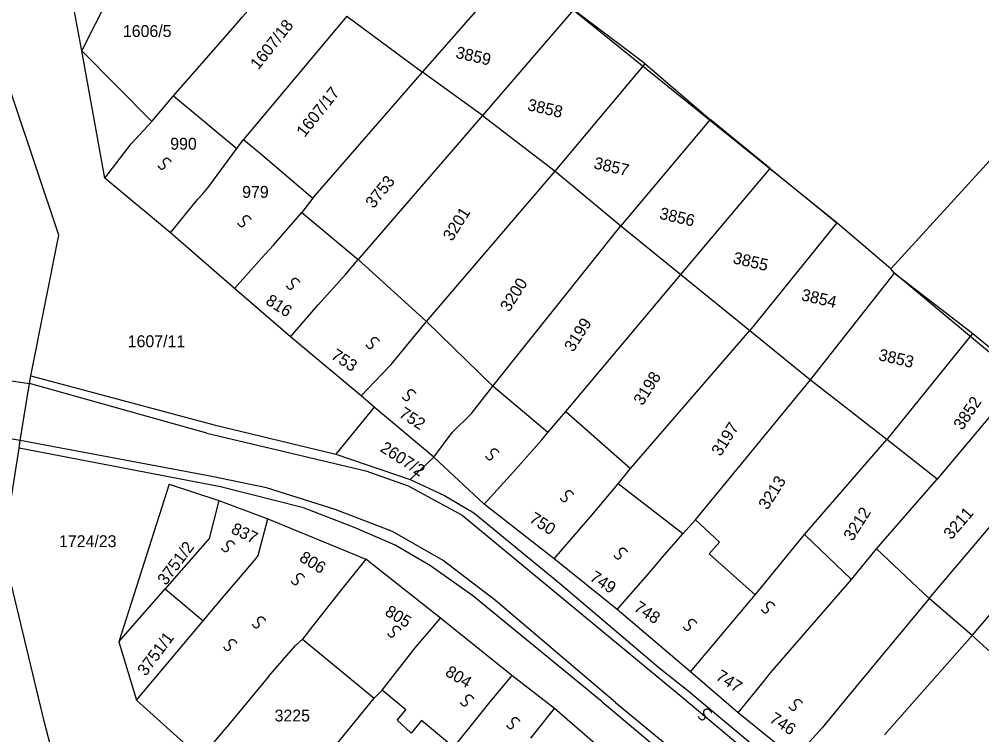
# Model space of a CAD drawing. Extents: x -581999 to -572728, y -1219553 to -1212032.
# Drawn here: x -578616.8 to -578454.7, y -1215447.1 to -1215326.8 of the extents above; entities that cross this region are included whole.
import ezdxf

# ---------------------------------------------------------------- set-up
doc = ezdxf.new("R2010")
doc.units = 0
for name, color, linetype in [('Vrstva 1', 7, 'Continuous'), ('Vrstva 2', 7, 'Continuous'), ('Vrstva 4', 7, 'Continuous'), ('Vrstva 6', 7, 'Continuous'), ('Vrstva 63', 7, 'Continuous')]:
    doc.layers.add(name, color=color, linetype=linetype)

msp = doc.modelspace()

# ---------------------------------------------------------------- linework, layer by layer
at = {"layer": 'Vrstva 1'}
for p, q in [((-578606.252, -1215332.04), (-578615.797, -1215279.788)), ((-578606.252, -1215332.04), (-578595.304, -1215310.421)), ((-578602.345, -1215353.491), (-578606.252, -1215332.04)), ((-578594.44, -1215343.93), (-578606.252, -1215332.04)), ((-578616.594, -1215397.628), (-578615.047, -1215388.059)), ((-578545.855, -1215427.531), (-578558.395, -1215417.606)), ((-578533.826, -1215437.135), (-578545.855, -1215427.531)), ((-578574.718, -1215437.276), (-578570.244, -1215432.113))]:
    msp.add_line(p, q, dxfattribs=at)
for points in [[(-578614.8, -1215386.733), (-578610.127, -1215363.104), (-578625.552, -1215317.149), (-578638.443, -1215277), (-578660.875, -1215206.543)], [(-578470.005, -1215368.724), (-578419.996, -1215313.968), (-578364.405, -1215360.703), (-578359.63, -1215364.861), (-578404.474, -1215421.622)], [(-578548.894, -1215335.635), (-578533.007, -1215317.54)], [(-578580.387, -1215327.793), (-578579.171, -1215326.365), (-578572.028, -1215318.28)], [(-578523.429, -1215325.172), (-578538.8, -1215342.955)], [(-578511.374, -1215334.248), (-578523.429, -1215325.172)], [(-578561.596, -1215326.225), (-578579.014, -1215346.957)], [(-578561.596, -1215326.225), (-578548.894, -1215335.635)], [(-578590.79, -1215339.631), (-578580.387, -1215327.793)], [(-578526.545, -1215352.298), (-578511.374, -1215334.248)], [(-578511.374, -1215334.248), (-578500.443, -1215343.601)], [(-578567.343, -1215356.878), (-578548.894, -1215335.635)], [(-578538.8, -1215342.955), (-578548.894, -1215335.635)], [(-578597.909, -1215347.696), (-578594.44, -1215343.93), (-578590.79, -1215339.631)], [(-578590.79, -1215339.631), (-578580.148, -1215348.51)], [(-578538.8, -1215342.955), (-578559.727, -1215367.161)], [(-578538.8, -1215342.955), (-578526.545, -1215352.298)], [(-578500.443, -1215343.601), (-578515.501, -1215361.486)], [(-578490.342, -1215351.838), (-578500.443, -1215343.601)], [(-578591.29, -1215362.681), (-578602.345, -1215353.491), (-578597.909, -1215347.696)], [(-578584.997, -1215355.131), (-578580.148, -1215348.51)], [(-578580.148, -1215348.51), (-578579.014, -1215346.957)], [(-578579.014, -1215346.957), (-578575.776, -1215349.701)], [(-578575.776, -1215349.701), (-578567.343, -1215356.878)], [(-578548.205, -1215377.626), (-578526.545, -1215352.298)], [(-578526.545, -1215352.298), (-578515.501, -1215361.486)], [(-578505.375, -1215369.692), (-578490.342, -1215351.838)], [(-578490.342, -1215351.838), (-578479.131, -1215361.016)], [(-578591.29, -1215362.681), (-578586.751, -1215357.096), (-578585.874, -1215356.114)], [(-578585.874, -1215356.114), (-578584.997, -1215355.131)], [(-578567.343, -1215356.878), (-578569.199, -1215359.257)], [(-578573.945, -1215364.737), (-578569.199, -1215359.257)], [(-578569.199, -1215359.257), (-578559.727, -1215367.161)], [(-578537.044, -1215388.461), (-578515.501, -1215361.486)], [(-578515.501, -1215361.486), (-578505.375, -1215369.692)], [(-578479.131, -1215361.016), (-578493.773, -1215379.106)], [(-578470.005, -1215368.724), (-578479.131, -1215361.016)], [(-578580.547, -1215372.077), (-578591.29, -1215362.681)], [(-578575.905, -1215366.907), (-578573.945, -1215364.737)], [(-578580.547, -1215372.077), (-578575.905, -1215366.907)], [(-578561.791, -1215369.643), (-578559.727, -1215367.161)], [(-578559.727, -1215367.161), (-578548.205, -1215377.626)], [(-578483.538, -1215387.437), (-578469.436, -1215369.468)], [(-578469.436, -1215369.468), (-578470.005, -1215368.724)], [(-578469.436, -1215369.468), (-578456.237, -1215379.595)], [(-578566.432, -1215374.811), (-578561.791, -1215369.643)], [(-578524.764, -1215392.742), (-578505.375, -1215369.692)], [(-578505.375, -1215369.692), (-578493.773, -1215379.106)], [(-578571.074, -1215380.187), (-578580.547, -1215372.077)], [(-578571.074, -1215380.187), (-578566.432, -1215374.811)], [(-578554.145, -1215384.833), (-578548.205, -1215377.626)], [(-578537.044, -1215388.461), (-578548.205, -1215377.626)], [(-578513.881, -1215402.358), (-578493.773, -1215379.106)], [(-578493.773, -1215379.106), (-578483.538, -1215387.437)], [(-578559.199, -1215390.103), (-578571.074, -1215380.187)], [(-578483.538, -1215387.437), (-578470.672, -1215397.474), (-578456.237, -1215379.595)], [(-578456.237, -1215379.595), (-578447.578, -1215386.69)], [(-578555.693, -1215386.383), (-578554.145, -1215384.833)], [(-578615.047, -1215388.059), (-578614.8, -1215386.733)], [(-578614.8, -1215386.733), (-578583.973, -1215394.99), (-578563.489, -1215399.933)], [(-578559.199, -1215390.103), (-578555.693, -1215386.383)], [(-578502.908, -1215410.958), (-578483.538, -1215387.437)], [(-578447.578, -1215386.69), (-578462.217, -1215404.152)], [(-578540.622, -1215393.077), (-578537.044, -1215388.461)], [(-578527.797, -1215396.276), (-578537.044, -1215388.461)], [(-578557.027, -1215392.021), (-578559.199, -1215390.103)], [(-578557.027, -1215392.021), (-578563.489, -1215399.933)], [(-578546.985, -1215400.41), (-578557.027, -1215392.021)], [(-578543.903, -1215396.261), (-578540.622, -1215393.077)], [(-578527.797, -1215396.276), (-578524.764, -1215392.742)], [(-578524.764, -1215392.742), (-578513.881, -1215402.358)], [(-578463.566, -1215424.184), (-578438.296, -1215394.446)], [(-578546.985, -1215400.41), (-578543.903, -1215396.261)], [(-578528.785, -1215397.496), (-578527.797, -1215396.276)], [(-578612.489, -1215445.07), (-578619.496, -1215416.092), (-578616.755, -1215398.896), (-578616.594, -1215397.628)], [(-578533.529, -1215402.87), (-578528.785, -1215397.496)], [(-578484.566, -1215413.419), (-578470.698, -1215397.462)], [(-578462.217, -1215404.152), (-578470.698, -1215397.462)], [(-578518.647, -1215441.616), (-578540.386, -1215423.773), (-578547.549, -1215418.731), (-578553.493, -1215415.217), (-578560.199, -1215412.314), (-578568.886, -1215408.953), (-578582.907, -1215405.439), (-578616.755, -1215398.896)], [(-578563.489, -1215399.933), (-578550.961, -1215404.178)], [(-578546.985, -1215400.41), (-578550.961, -1215404.178)], [(-578538.479, -1215408.347), (-578546.985, -1215400.41)], [(-578456.35, -1215430.437), (-578436.168, -1215406.937), (-578430.602, -1215400.268)], [(-578538.479, -1215408.347), (-578533.529, -1215402.87)], [(-578515.944, -1215404.943), (-578513.881, -1215402.358)], [(-578591.531, -1215404.968), (-578599.971, -1215431.515)], [(-578591.531, -1215404.968), (-578583.169, -1215407.743)], [(-578550.961, -1215404.178), (-578545.195, -1215406.88), (-578540.223, -1215409.775), (-578525.508, -1215421.836), (-578509.102, -1215435.826), (-578504.23, -1215439.686)], [(-578520.628, -1215410.507), (-578515.944, -1215404.943)], [(-578505.073, -1215413.334), (-578515.944, -1215404.943)], [(-578472.452, -1215415.849), (-578462.217, -1215404.152)], [(-578583.169, -1215407.743), (-578584.817, -1215414.089)], [(-578583.169, -1215407.743), (-578574.905, -1215410.811)], [(-578526.712, -1215417.534), (-578538.479, -1215408.347)], [(-578576.943, -1215417.545), (-578576.554, -1215416.961), (-578574.905, -1215410.811)], [(-578574.905, -1215410.811), (-578558.395, -1215417.606)], [(-578526.712, -1215417.534), (-578521.453, -1215411.437)], [(-578521.453, -1215411.437), (-578520.628, -1215410.507)], [(-578505.073, -1215413.334), (-578502.908, -1215410.958)], [(-578502.908, -1215410.958), (-578498.886, -1215414.711), (-578500.639, -1215416.673), (-578492.865, -1215423.599)], [(-578508.476, -1215417.26), (-578505.073, -1215413.334)], [(-578584.817, -1215414.089), (-578592.2, -1215422.558)], [(-578493.431, -1215424.271), (-578492.865, -1215423.599), (-578492.297, -1215422.928), (-578484.566, -1215413.419)], [(-578484.566, -1215413.419), (-578476.65, -1215420.991)], [(-578476.65, -1215420.991), (-578472.452, -1215415.849)], [(-578472.452, -1215415.849), (-578463.566, -1215424.184)], [(-578585.781, -1215427.963), (-578582.551, -1215424.087), (-578576.943, -1215417.545)], [(-578558.395, -1215417.606), (-578562.96, -1215423.252)], [(-578516.106, -1215426.043), (-578526.712, -1215417.534)], [(-578510.951, -1215420.153), (-578508.476, -1215417.26)], [(-578516.106, -1215426.043), (-578510.951, -1215420.153)], [(-578490.266, -1215436.716), (-578476.65, -1215420.991)], [(-578599.971, -1215431.515), (-578592.2, -1215422.558)], [(-578592.2, -1215422.558), (-578585.781, -1215427.963)], [(-578562.96, -1215423.252), (-578566.942, -1215428.317)], [(-578499.926, -1215432.02), (-578493.431, -1215424.271)], [(-578463.566, -1215424.184), (-578477.791, -1215441.334)], [(-578456.35, -1215430.437), (-578463.566, -1215424.184)], [(-578503.741, -1215436.566), (-578516.106, -1215426.043)], [(-578550.128, -1215432.495), (-578545.855, -1215427.531)], [(-578597.048, -1215441.301), (-578585.781, -1215427.963)], [(-578566.942, -1215428.317), (-578569.078, -1215431.042)], [(-578569.078, -1215431.042), (-578570.244, -1215432.113)], [(-578569.078, -1215431.042), (-578557.023, -1215440.965)], [(-578471.09, -1215447.169), (-578456.35, -1215430.437)], [(-578447.102, -1215438.847), (-578456.35, -1215430.437)], [(-578599.971, -1215431.515), (-578597.048, -1215441.301)], [(-578555.663, -1215439.603), (-578550.128, -1215432.495)], [(-578503.741, -1215436.566), (-578499.926, -1215432.02)], [(-578574.718, -1215437.276), (-578581.217, -1215445.06)], [(-578533.826, -1215437.135), (-578537.517, -1215441.612)], [(-578519.857, -1215448.603), (-578526.636, -1215442.735), (-578533.826, -1215437.135)], [(-578495.73, -1215443.433), (-578503.741, -1215436.566)], [(-578495.73, -1215443.433), (-578491.504, -1215438.266), (-578490.885, -1215437.491)], [(-578490.885, -1215437.491), (-578490.266, -1215436.716)], [(-578557.023, -1215440.965), (-578555.663, -1215439.603)], [(-578551.677, -1215442.943), (-578555.663, -1215439.603)], [(-578504.23, -1215439.686), (-578419.077, -1215510.839)], [(-578597.048, -1215441.301), (-578586.268, -1215450.998)], [(-578573.725, -1215461.408), (-578570.297, -1215457.307), (-578557.023, -1215440.965)], [(-578537.517, -1215441.612), (-578538.876, -1215443.267)], [(-578518.647, -1215441.616), (-578481.363, -1215472.872)], [(-578477.791, -1215441.334), (-578481.605, -1215445.983)], [(-578543.634, -1215449.206), (-578549.054, -1215444.712), (-578550.802, -1215446.854), (-578553.134, -1215444.694), (-578551.677, -1215442.943)], [(-578538.876, -1215443.267), (-578543.634, -1215449.206)], [(-578530.616, -1215447.699), (-578526.636, -1215442.735)], [(-578486.244, -1215451.147), (-578495.73, -1215443.433)], [(-578609.763, -1215455.623), (-578612.489, -1215445.07)], [(-578581.217, -1215445.06), (-578586.268, -1215450.998)], [(-578481.605, -1215445.983), (-578486.244, -1215451.147)]]:
    msp.add_lwpolyline(points, dxfattribs=at)
at = {"layer": 'Vrstva 4'}
for points in [[(-578621.211, -1215387.123), (-578615.047, -1215388.059)], [(-578585.165, -1215396.363), (-578615.047, -1215388.059)], [(-578616.594, -1215397.628), (-578623.694, -1215396.422)], [(-578585.165, -1215396.363), (-578558.419, -1215402.731), (-578551.26, -1215405.24), (-578542.212, -1215410.161), (-578505.224, -1215440.747)], [(-578584.369, -1215403.696), (-578616.594, -1215397.628)], [(-578516.36, -1215441.712), (-578536.576, -1215424.537), (-578545.415, -1215417.814), (-578553.95, -1215412.925), (-578563.552, -1215409.258), (-578575.135, -1215405.592), (-578584.369, -1215403.696)], [(-578505.224, -1215440.747), (-578421.464, -1215511.032)], [(-578516.36, -1215441.712), (-578479.233, -1215472.341)]]:
    msp.add_lwpolyline(points, dxfattribs=at)
at = {"layer": 'Vrstva 6'}
for points in [[(-578593.433, -1215351.395), (-578592.953, -1215352.102), (-578592.259, -1215351.791), (-578592.182, -1215351.391), (-578592.418, -1215351.046), (-578592.503, -1215350.714), (-578592.421, -1215350.424), (-578592.277, -1215350.244), (-578592.041, -1215350.116), (-578591.676, -1215350.152), (-578591.249, -1215350.591), (-578591.194, -1215350.764)], [(-578580.006, -1215361.056), (-578579.526, -1215361.763), (-578578.832, -1215361.452), (-578578.755, -1215361.052), (-578578.991, -1215360.707), (-578579.076, -1215360.375), (-578578.994, -1215360.085), (-578578.85, -1215359.905), (-578578.614, -1215359.777), (-578578.249, -1215359.813), (-578577.822, -1215360.252), (-578577.767, -1215360.425)], [(-578571.833, -1215371.595), (-578571.353, -1215372.302), (-578570.659, -1215371.991), (-578570.582, -1215371.591), (-578570.818, -1215371.246), (-578570.903, -1215370.914), (-578570.821, -1215370.624), (-578570.677, -1215370.444), (-578570.441, -1215370.316), (-578570.076, -1215370.352), (-578569.649, -1215370.791), (-578569.594, -1215370.964)], [(-578558.407, -1215381.549), (-578557.927, -1215382.256), (-578557.233, -1215381.945), (-578557.156, -1215381.545), (-578557.392, -1215381.2), (-578557.477, -1215380.868), (-578557.395, -1215380.578), (-578557.251, -1215380.398), (-578557.015, -1215380.27), (-578556.65, -1215380.306), (-578556.223, -1215380.745), (-578556.168, -1215380.918)], [(-578552.277, -1215390.332), (-578551.797, -1215391.039), (-578551.103, -1215390.728), (-578551.026, -1215390.328), (-578551.262, -1215389.983), (-578551.347, -1215389.651), (-578551.265, -1215389.361), (-578551.121, -1215389.181), (-578550.885, -1215389.053), (-578550.52, -1215389.089), (-578550.093, -1215389.528), (-578550.038, -1215389.701)], [(-578538.267, -1215400.286), (-578537.787, -1215400.993), (-578537.093, -1215400.682), (-578537.016, -1215400.282), (-578537.252, -1215399.937), (-578537.337, -1215399.605), (-578537.255, -1215399.315), (-578537.111, -1215399.135), (-578536.875, -1215399.007), (-578536.51, -1215399.043), (-578536.083, -1215399.482), (-578536.028, -1215399.655)], [(-578525.716, -1215407.312), (-578525.236, -1215408.019), (-578524.542, -1215407.708), (-578524.465, -1215407.308), (-578524.701, -1215406.963), (-578524.786, -1215406.631), (-578524.704, -1215406.341), (-578524.56, -1215406.161), (-578524.324, -1215406.033), (-578523.959, -1215406.069), (-578523.532, -1215406.508), (-578523.477, -1215406.681)], [(-578582.743, -1215415.747), (-578582.263, -1215416.454), (-578581.569, -1215416.143), (-578581.492, -1215415.743), (-578581.728, -1215415.398), (-578581.813, -1215415.066), (-578581.731, -1215414.776), (-578581.587, -1215414.596), (-578581.351, -1215414.468), (-578580.986, -1215414.504), (-578580.559, -1215414.943), (-578580.504, -1215415.116)], [(-578516.667, -1215416.973), (-578516.187, -1215417.68), (-578515.493, -1215417.369), (-578515.416, -1215416.969), (-578515.652, -1215416.624), (-578515.737, -1215416.292), (-578515.655, -1215416.002), (-578515.511, -1215415.822), (-578515.275, -1215415.694), (-578514.91, -1215415.73), (-578514.483, -1215416.169), (-578514.428, -1215416.342)], [(-578571.006, -1215421.283), (-578570.526, -1215421.99), (-578569.832, -1215421.679), (-578569.755, -1215421.279), (-578569.991, -1215420.934), (-578570.076, -1215420.602), (-578569.994, -1215420.312), (-578569.85, -1215420.132), (-578569.614, -1215420.004), (-578569.249, -1215420.04), (-578568.822, -1215420.479), (-578568.767, -1215420.652)], [(-578491.857, -1215426.048), (-578491.377, -1215426.755), (-578490.683, -1215426.444), (-578490.606, -1215426.044), (-578490.842, -1215425.699), (-578490.927, -1215425.367), (-578490.845, -1215425.077), (-578490.701, -1215424.897), (-578490.465, -1215424.769), (-578490.1, -1215424.805), (-578489.673, -1215425.244), (-578489.618, -1215425.417)], [(-578577.565, -1215428.55), (-578577.085, -1215429.257), (-578576.391, -1215428.946), (-578576.314, -1215428.546), (-578576.55, -1215428.201), (-578576.635, -1215427.869), (-578576.553, -1215427.579), (-578576.409, -1215427.399), (-578576.173, -1215427.271), (-578575.808, -1215427.307), (-578575.381, -1215427.746), (-578575.326, -1215427.919)], [(-578504.992, -1215428.976), (-578504.512, -1215429.683), (-578503.818, -1215429.372), (-578503.741, -1215428.972), (-578503.977, -1215428.627), (-578504.062, -1215428.295), (-578503.98, -1215428.005), (-578503.836, -1215427.825), (-578503.6, -1215427.697), (-578503.235, -1215427.733), (-578502.808, -1215428.172), (-578502.753, -1215428.345)], [(-578554.782, -1215430.107), (-578554.302, -1215430.814), (-578553.608, -1215430.503), (-578553.531, -1215430.103), (-578553.767, -1215429.758), (-578553.852, -1215429.426), (-578553.77, -1215429.136), (-578553.626, -1215428.956), (-578553.39, -1215428.828), (-578553.025, -1215428.864), (-578552.598, -1215429.303), (-578552.543, -1215429.476)], [(-578582.397, -1215432.357), (-578581.917, -1215433.064), (-578581.223, -1215432.753), (-578581.146, -1215432.353), (-578581.382, -1215432.008), (-578581.467, -1215431.676), (-578581.385, -1215431.386), (-578581.241, -1215431.206), (-578581.005, -1215431.078), (-578580.64, -1215431.114), (-578580.213, -1215431.553), (-578580.158, -1215431.726)], [(-578542.528, -1215441.7), (-578542.048, -1215442.407), (-578541.354, -1215442.096), (-578541.277, -1215441.696), (-578541.513, -1215441.351), (-578541.598, -1215441.019), (-578541.516, -1215440.729), (-578541.372, -1215440.549), (-578541.136, -1215440.421), (-578540.771, -1215440.457), (-578540.344, -1215440.896), (-578540.289, -1215441.069)], [(-578487.187, -1215442.443), (-578486.707, -1215443.15), (-578486.013, -1215442.839), (-578485.936, -1215442.439), (-578486.172, -1215442.094), (-578486.257, -1215441.762), (-578486.175, -1215441.472), (-578486.031, -1215441.292), (-578485.795, -1215441.164), (-578485.43, -1215441.2), (-578485.003, -1215441.639), (-578484.948, -1215441.812)], [(-578502.486, -1215444.044), (-578502.006, -1215444.751), (-578501.312, -1215444.44), (-578501.235, -1215444.04), (-578501.471, -1215443.695), (-578501.556, -1215443.363), (-578501.474, -1215443.073), (-578501.33, -1215442.893), (-578501.094, -1215442.765), (-578500.729, -1215442.801), (-578500.302, -1215443.24), (-578500.247, -1215443.413)], [(-578534.761, -1215445.506), (-578534.281, -1215446.213), (-578533.587, -1215445.902), (-578533.51, -1215445.502), (-578533.746, -1215445.157), (-578533.831, -1215444.825), (-578533.749, -1215444.535), (-578533.605, -1215444.355), (-578533.369, -1215444.227), (-578533.004, -1215444.263), (-578532.577, -1215444.702), (-578532.522, -1215444.875)]]:
    msp.add_open_spline(points, degree=2, dxfattribs=at)
at = {"layer": 'Vrstva 63'}
for p, q in [((-578479.131, -1215361.016), (-578533.007, -1215317.54)), ((-578470.005, -1215368.724), (-578479.131, -1215361.016)), ((-578469.436, -1215369.468), (-578470.005, -1215368.724)), ((-578362.034, -1215459.321), (-578469.436, -1215369.468))]:
    msp.add_line(p, q, dxfattribs=at)

# ---------------------------------------------------------------- texts
at = {"layer": 'Vrstva 2'}
for s, rotation, p in [('1607/18', 51.5236, (-578576.501, -1215335.369)), ('3859', 346.89894, (-578543.422, -1215333.216)), ('1607/17', 51.5236, (-578568.719, -1215346.73)), ('3858', 346.89894, (-578531.338, -1215342.019)), ('3857', 346.89894, (-578520.168, -1215351.823)), ('3753', 51.5236, (-578557.099, -1215358.705)), ('3201', 57.6048, (-578543.908, -1215364.231)), ('3856', 346.89894, (-578509.112, -1215360.296)), ('3855', 346.89894, (-578496.737, -1215367.783)), ('3200', 57.6048, (-578534.274, -1215376.127)), ('3854', 346.89894, (-578485.23, -1215373.999)), ('816', 327.11662, (-578575.435, -1215374.549)), ('3199', 57.6048, (-578523.492, -1215382.862)), ('753', 327.11662, (-578564.434, -1215383.729)), ('3853', 346.89894, (-578472.228, -1215384.085)), ('3198', 57.6048, (-578511.824, -1215391.869)), ('3852', 55.8802, (-578457.996, -1215396.023)), ('752', 327.11662, (-578552.986, -1215393.526)), ('3197', 57.6048, (-578498.694, -1215400.403)), ('2607/2', 327.11662, (-578556.163, -1215399.334)), ('3213', 57.6048, (-578490.787, -1215409.424)), ('750', 327.11662, (-578531.061, -1215411.213)), ('3212', 57.6048, (-578476.478, -1215414.686)), ('3211', 49.32832, (-578459.847, -1215414.427)), ('837', 334.1232, (-578581.257, -1215413.132)), ('3751/2', 53.48913, (-578592.072, -1215422.126)), ('806', 328.77499, (-578569.761, -1215417.81)), ('749', 327.11662, (-578520.884, -1215421.059)), ('748', 327.11662, (-578513.437, -1215426.153)), ('805', 328.77499, (-578555.357, -1215426.905)), ('3751/1', 53.48913, (-578595.469, -1215437.374)), ('804', 328.77499, (-578545.205, -1215437.059)), ('747', 327.11662, (-578499.652, -1215437.724)), ('746', 327.11662, (-578490.61, -1215444.876))]:
    msp.add_text(s, height=2, rotation=rotation, dxfattribs=at).set_placement(p)
for s, p in [('1606/5', (-578599.308, -1215329.739)), ('990', (-578591.346, -1215348.698)), ('979', (-578579.234, -1215356.799)), ('1607/11', (-578598.496, -1215381.926)), ('1724/23', (-578610.065, -1215415.568)), ('3225', (-578573.77, -1215444.9))]:
    msp.add_text(s, height=2, dxfattribs=at).set_placement(p)

doc.saveas('drawing.dxf')
